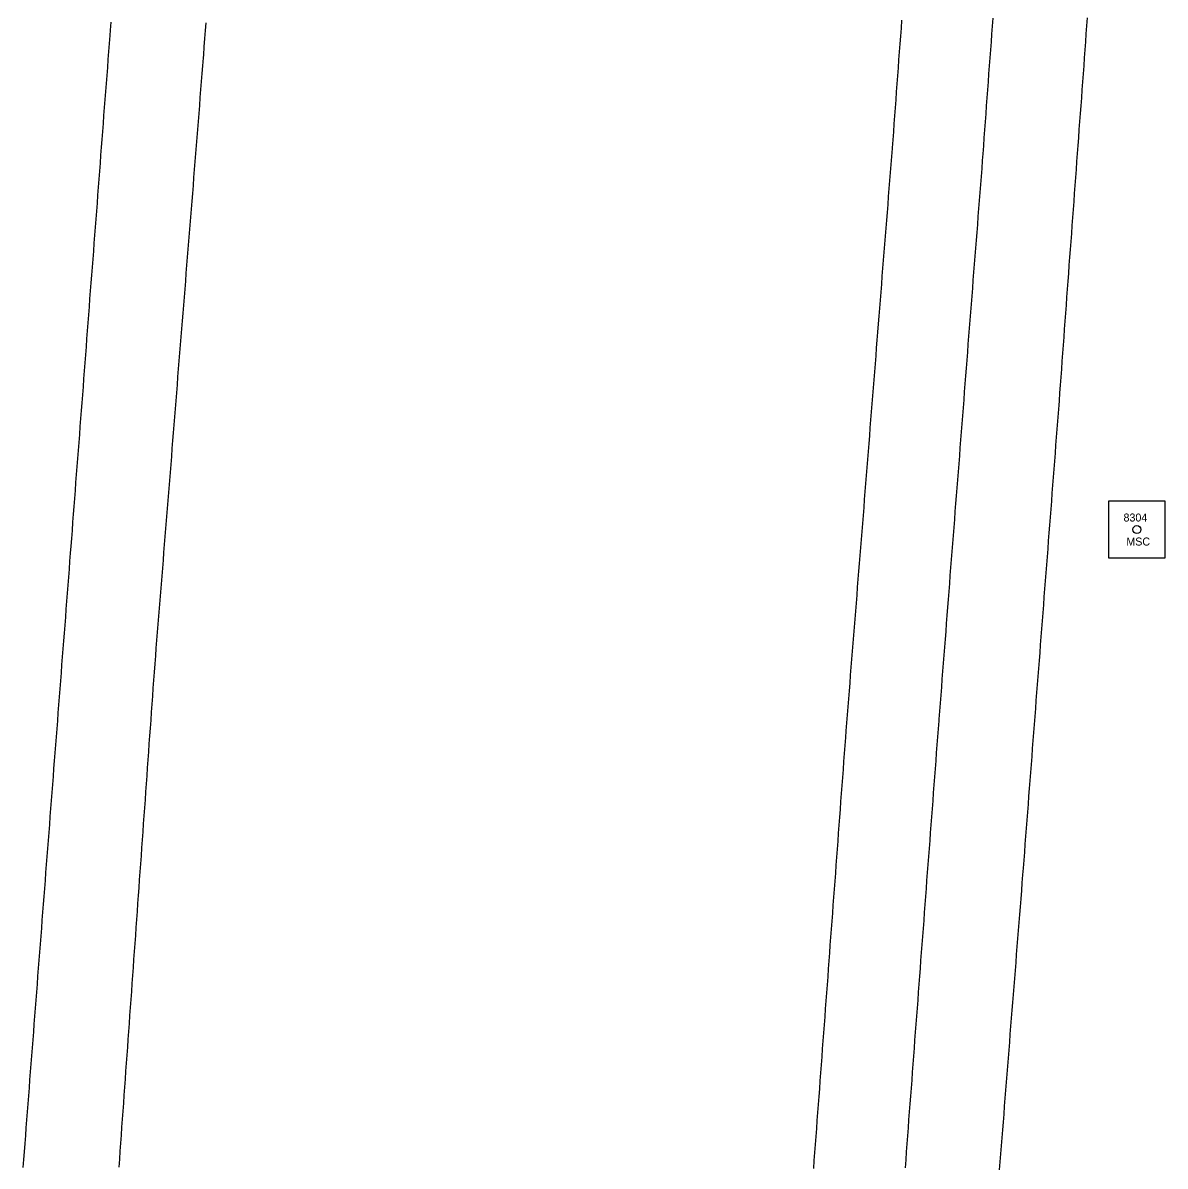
# Model space of a CAD drawing. Extents: x 205929 to 2357175, y -1785700 to 846739.
# Drawn here: x 2023419.5 to 2023562.3, y 809503.6 to 809646.4 of the extents above; entities that cross this region are included whole.
import ezdxf

# ---------------------------------------------------------------- set-up
doc = ezdxf.new("R2010")
doc.units = 0
for name, color, linetype in [('RD_HC_Survey', 7, 'Continuous'), ('RD_HC_txCode', 7, 'Continuous'), ('RD_Sketch1', 7, 'Continuous'), ('RD_SMD_Locator', 7, 'Continuous')]:
    doc.layers.add(name, color=color, linetype=linetype)

msp = doc.modelspace()

# ---------------------------------------------------------------- linework, layer by layer
at = {"layer": 'RD_HC_Survey'}
msp.add_lwpolyline([(2023562.28, 809586.65), (2023555.21, 809586.65), (2023555.21, 809579.58), (2023562.28, 809579.58)], close=True, dxfattribs=at)
msp.add_circle((2023558.75, 809583.11), 0.5, dxfattribs=at)
at = {"layer": 'RD_Sketch1'}
for points in [[(2023430.49, 809646.49), (2023430.41, 809645.49), (2023430.36, 809644.82), (2023430.29, 809643.83), (2023430.21, 809642.83), (2023430.13, 809641.83), (2023430.06, 809640.84), (2023429.98, 809639.84), (2023429.91, 809638.84), (2023429.83, 809637.85), (2023429.75, 809636.85), (2023429.68, 809635.85), (2023429.6, 809634.85), (2023429.53, 809633.86), (2023429.45, 809632.86), (2023429.37, 809631.86), (2023429.3, 809630.87), (2023429.22, 809629.87), (2023429.15, 809628.87), (2023429.07, 809627.88), (2023428.99, 809626.88), (2023428.92, 809625.88), (2023428.84, 809624.88), (2023428.77, 809623.89), (2023428.69, 809622.89), (2023428.61, 809621.89), (2023428.54, 809620.9), (2023428.46, 809619.9), (2023428.39, 809618.9), (2023428.31, 809617.91), (2023428.23, 809616.91), (2023428.16, 809615.91), (2023428.08, 809614.91), (2023428.01, 809613.92), (2023427.93, 809612.92), (2023427.85, 809611.92), (2023427.78, 809610.93), (2023427.7, 809609.93), (2023427.63, 809608.93), (2023427.55, 809607.94), (2023427.47, 809606.94), (2023427.4, 809605.94), (2023427.32, 809604.95), (2023427.25, 809603.95), (2023427.17, 809602.95), (2023427.09, 809601.95), (2023427.02, 809600.96), (2023426.94, 809599.96), (2023426.87, 809598.96), (2023426.79, 809597.97), (2023426.71, 809596.97), (2023426.64, 809595.97), (2023426.56, 809594.98), (2023426.48, 809593.98), (2023426.41, 809592.98), (2023426.33, 809591.98), (2023426.26, 809590.99), (2023426.18, 809589.99), (2023426.1, 809588.99), (2023426.03, 809588), (2023425.95, 809587), (2023425.88, 809586), (2023425.8, 809585.01), (2023425.72, 809584.01), (2023425.65, 809583.01), (2023425.57, 809582.01), (2023425.5, 809581.02), (2023425.5, 809581.02), (2023425.43, 809580.15), (2023425.35, 809579.16), (2023425.28, 809578.16), (2023425.2, 809577.16), (2023425.12, 809576.16), (2023425.05, 809575.17), (2023424.97, 809574.17), (2023424.89, 809573.17), (2023424.81, 809572.18), (2023424.74, 809571.18), (2023424.66, 809570.18), (2023424.58, 809569.19), (2023424.51, 809568.19), (2023424.43, 809567.19), (2023424.35, 809566.2), (2023424.27, 809565.2), (2023424.2, 809564.2), (2023424.12, 809563.2), (2023424.04, 809562.21), (2023423.97, 809561.21), (2023423.89, 809560.21), (2023423.81, 809559.22), (2023423.74, 809558.22), (2023423.66, 809557.22), (2023423.58, 809556.23), (2023423.5, 809555.23), (2023423.43, 809554.23), (2023423.35, 809553.24), (2023423.27, 809552.24), (2023423.2, 809551.24), (2023423.12, 809550.24), (2023423.04, 809549.25), (2023422.97, 809548.25), (2023422.89, 809547.25), (2023422.81, 809546.26), (2023422.73, 809545.26), (2023422.66, 809544.26), (2023422.58, 809543.27), (2023422.5, 809542.27), (2023422.43, 809541.27), (2023422.35, 809540.28), (2023422.27, 809539.28), (2023422.19, 809538.28), (2023422.12, 809537.28), (2023422.04, 809536.29), (2023421.96, 809535.29), (2023421.89, 809534.29), (2023421.81, 809533.3), (2023421.73, 809532.3), (2023421.66, 809531.3), (2023421.58, 809530.31), (2023421.5, 809529.31), (2023421.42, 809528.31), (2023421.35, 809527.32), (2023421.27, 809526.32), (2023421.19, 809525.32), (2023421.12, 809524.32), (2023421.04, 809523.33), (2023420.96, 809522.33), (2023420.89, 809521.33), (2023420.81, 809520.34), (2023420.73, 809519.34), (2023420.65, 809518.34), (2023420.58, 809517.35), (2023420.58, 809517.35), (2023420.5, 809516.35), (2023420.42, 809515.35), (2023420.35, 809514.36), (2023420.27, 809513.36), (2023420.19, 809512.36), (2023420.11, 809511.36), (2023420.04, 809510.37), (2023419.96, 809509.37), (2023419.88, 809508.37), (2023419.81, 809507.38), (2023419.73, 809506.38), (2023419.65, 809505.38), (2023419.58, 809504.39), (2023419.5, 809503.39)], [(2023442.36, 809646.43), (2023442.29, 809645.44), (2023442.21, 809644.44), (2023442.14, 809643.44), (2023442.07, 809642.44), (2023442.04, 809642.06), (2023441.96, 809641.06), (2023441.88, 809640.07), (2023441.8, 809639.07), (2023441.72, 809638.07), (2023441.64, 809637.08), (2023441.56, 809636.08), (2023441.48, 809635.08), (2023441.4, 809634.09), (2023441.32, 809633.09), (2023441.24, 809632.09), (2023441.17, 809631.1), (2023441.09, 809630.1), (2023441.01, 809629.1), (2023440.93, 809628.11), (2023440.85, 809627.11), (2023440.77, 809626.11), (2023440.69, 809625.11), (2023440.61, 809624.12), (2023440.53, 809623.12), (2023440.45, 809622.12), (2023440.37, 809621.13), (2023440.29, 809620.13), (2023440.21, 809619.13), (2023440.13, 809618.14), (2023440.05, 809617.14), (2023439.97, 809616.14), (2023439.89, 809615.15), (2023439.81, 809614.15), (2023439.73, 809613.15), (2023439.65, 809612.16), (2023439.57, 809611.16), (2023439.49, 809610.16), (2023439.41, 809609.17), (2023439.33, 809608.17), (2023439.25, 809607.17), (2023439.17, 809606.18), (2023439.09, 809605.18), (2023439.01, 809604.18), (2023438.93, 809603.19), (2023438.85, 809602.19), (2023438.77, 809601.19), (2023438.69, 809600.2), (2023438.61, 809599.2), (2023438.53, 809598.2), (2023438.46, 809597.21), (2023438.38, 809596.21), (2023438.3, 809595.21), (2023438.22, 809594.22), (2023438.14, 809593.22), (2023438.06, 809592.22), (2023437.98, 809591.23), (2023437.9, 809590.23), (2023437.82, 809589.23), (2023437.74, 809588.24), (2023437.66, 809587.24), (2023437.58, 809586.24), (2023437.5, 809585.25), (2023437.42, 809584.25), (2023437.34, 809583.25), (2023437.26, 809582.26), (2023437.18, 809581.26), (2023437.1, 809580.26), (2023437.02, 809579.27), (2023436.94, 809578.27), (2023436.94, 809578.27), (2023436.86, 809577.27), (2023436.78, 809576.28), (2023436.7, 809575.28), (2023436.62, 809574.28), (2023436.54, 809573.29), (2023436.46, 809572.29), (2023436.38, 809571.29), (2023436.3, 809570.3), (2023436.22, 809569.3), (2023436.14, 809568.3), (2023436.06, 809567.31), (2023435.98, 809566.31), (2023435.9, 809565.29), (2023435.83, 809564.3), (2023435.76, 809563.3), (2023435.69, 809562.3), (2023435.62, 809561.3), (2023435.55, 809560.31), (2023435.48, 809559.31), (2023435.41, 809558.31), (2023435.33, 809557.32), (2023435.26, 809556.32), (2023435.19, 809555.32), (2023435.12, 809554.32), (2023435.05, 809553.33), (2023434.98, 809552.33), (2023434.91, 809551.33), (2023434.84, 809550.33), (2023434.77, 809549.34), (2023434.69, 809548.34), (2023434.62, 809547.34), (2023434.55, 809546.34), (2023434.48, 809545.35), (2023434.41, 809544.35), (2023434.34, 809543.35), (2023434.27, 809542.35), (2023434.2, 809541.36), (2023434.13, 809540.36), (2023434.05, 809539.36), (2023433.98, 809538.36), (2023433.91, 809537.37), (2023433.84, 809536.37), (2023433.77, 809535.37), (2023433.7, 809534.37), (2023433.63, 809533.38), (2023433.56, 809532.38), (2023433.49, 809531.38), (2023433.41, 809530.38), (2023433.34, 809529.39), (2023433.27, 809528.39), (2023433.2, 809527.39), (2023433.13, 809526.4), (2023433.06, 809525.4), (2023432.99, 809524.4), (2023432.92, 809523.4), (2023432.85, 809522.41), (2023432.77, 809521.41), (2023432.7, 809520.41), (2023432.63, 809519.41), (2023432.56, 809518.42), (2023432.49, 809517.42), (2023432.42, 809516.42), (2023432.35, 809515.42), (2023432.28, 809514.43), (2023432.28, 809514.43), (2023432.21, 809513.43), (2023432.13, 809512.43), (2023432.06, 809511.43), (2023431.99, 809510.44), (2023431.92, 809509.44), (2023431.85, 809508.44), (2023431.78, 809507.44), (2023431.71, 809506.45), (2023431.64, 809505.45), (2023431.57, 809504.45), (2023431.5, 809503.45)], [(2023529.34, 809646.77), (2023529.27, 809645.77), (2023529.19, 809644.77), (2023529.12, 809643.78), (2023529.05, 809642.78), (2023528.97, 809641.78), (2023528.9, 809640.79), (2023528.82, 809639.79), (2023528.75, 809638.79), (2023528.68, 809637.8), (2023528.6, 809636.8), (2023528.53, 809635.8), (2023528.46, 809634.8), (2023528.38, 809633.81), (2023528.31, 809632.81), (2023528.23, 809631.81), (2023528.16, 809630.82), (2023528.15, 809630.72), (2023528.07, 809629.72), (2023527.99, 809628.72), (2023527.92, 809627.73), (2023527.84, 809626.73), (2023527.76, 809625.73), (2023527.68, 809624.74), (2023527.6, 809623.74), (2023527.52, 809622.74), (2023527.44, 809621.75), (2023527.36, 809620.75), (2023527.28, 809619.75), (2023527.2, 809618.76), (2023527.13, 809617.76), (2023527.05, 809616.76), (2023526.97, 809615.76), (2023526.89, 809614.77), (2023526.81, 809613.77), (2023526.73, 809612.77), (2023526.65, 809611.78), (2023526.57, 809610.78), (2023526.49, 809609.78), (2023526.41, 809608.79), (2023526.33, 809607.79), (2023526.26, 809606.79), (2023526.18, 809605.8), (2023526.1, 809604.8), (2023526.02, 809603.8), (2023525.94, 809602.81), (2023525.86, 809601.81), (2023525.78, 809600.81), (2023525.7, 809599.82), (2023525.62, 809598.82), (2023525.54, 809597.82), (2023525.46, 809596.83), (2023525.39, 809595.83), (2023525.31, 809594.83), (2023525.23, 809593.84), (2023525.15, 809592.84), (2023525.07, 809591.84), (2023524.99, 809590.85), (2023524.91, 809589.85), (2023524.83, 809588.85), (2023524.75, 809587.86), (2023524.67, 809586.86), (2023524.6, 809585.86), (2023524.52, 809584.87), (2023524.44, 809583.87), (2023524.36, 809582.87), (2023524.28, 809581.87), (2023524.2, 809580.88), (2023524.12, 809579.88), (2023524.04, 809578.88), (2023523.96, 809577.89), (2023523.88, 809576.89), (2023523.8, 809575.89), (2023523.73, 809574.9), (2023523.65, 809573.9), (2023523.57, 809572.9), (2023523.49, 809571.91), (2023523.41, 809570.91), (2023523.33, 809569.91), (2023523.25, 809568.92), (2023523.17, 809567.92), (2023523.09, 809566.92), (2023523.09, 809566.92), (2023523.01, 809565.93), (2023522.93, 809564.93), (2023522.86, 809563.93), (2023522.78, 809562.94), (2023522.7, 809561.94), (2023522.62, 809560.94), (2023522.54, 809559.95), (2023522.46, 809558.95), (2023522.38, 809557.95), (2023522.32, 809557.13), (2023522.24, 809556.13), (2023522.17, 809555.13), (2023522.09, 809554.14), (2023522.02, 809553.14), (2023521.95, 809552.14), (2023521.87, 809551.15), (2023521.8, 809550.15), (2023521.72, 809549.15), (2023521.65, 809548.15), (2023521.58, 809547.16), (2023521.5, 809546.16), (2023521.43, 809545.16), (2023521.35, 809544.17), (2023521.28, 809543.17), (2023521.21, 809542.17), (2023521.13, 809541.17), (2023521.06, 809540.18), (2023520.98, 809539.18), (2023520.91, 809538.18), (2023520.84, 809537.19), (2023520.76, 809536.19), (2023520.69, 809535.19), (2023520.61, 809534.19), (2023520.54, 809533.2), (2023520.47, 809532.2), (2023520.39, 809531.2), (2023520.32, 809530.21), (2023520.24, 809529.21), (2023520.17, 809528.21), (2023520.1, 809527.21), (2023520.02, 809526.22), (2023519.95, 809525.22), (2023519.87, 809524.22), (2023519.8, 809523.22), (2023519.73, 809522.23), (2023519.65, 809521.23), (2023519.58, 809520.23), (2023519.5, 809519.24), (2023519.43, 809518.24), (2023519.36, 809517.24), (2023519.28, 809516.24), (2023519.21, 809515.25), (2023519.13, 809514.25), (2023519.06, 809513.25), (2023518.99, 809512.26), (2023518.91, 809511.26), (2023518.84, 809510.26), (2023518.76, 809509.26), (2023518.69, 809508.27), (2023518.62, 809507.27), (2023518.54, 809506.27), (2023518.47, 809505.28), (2023518.39, 809504.28), (2023518.32, 809503.28)], [(2023540.73, 809647.02), (2023540.66, 809646.02), (2023540.59, 809645.02), (2023540.52, 809644.03), (2023540.44, 809643.03), (2023540.37, 809642.03), (2023540.3, 809641.04), (2023540.22, 809640.04), (2023540.15, 809639.04), (2023540.08, 809638.05), (2023540, 809637.05), (2023539.93, 809636.05), (2023539.86, 809635.05), (2023539.78, 809634.06), (2023539.71, 809633.06), (2023539.64, 809632.06), (2023539.56, 809631.07), (2023539.49, 809630.07), (2023539.43, 809629.22), (2023539.35, 809628.22), (2023539.27, 809627.22), (2023539.2, 809626.22), (2023539.12, 809625.23), (2023539.04, 809624.23), (2023538.96, 809623.23), (2023538.88, 809622.24), (2023538.81, 809621.24), (2023538.73, 809620.24), (2023538.65, 809619.25), (2023538.57, 809618.25), (2023538.5, 809617.25), (2023538.42, 809616.26), (2023538.34, 809615.26), (2023538.26, 809614.26), (2023538.19, 809613.26), (2023538.11, 809612.27), (2023538.03, 809611.27), (2023537.95, 809610.27), (2023537.88, 809609.28), (2023537.8, 809608.28), (2023537.72, 809607.28), (2023537.64, 809606.29), (2023537.57, 809605.29), (2023537.49, 809604.29), (2023537.41, 809603.29), (2023537.33, 809602.3), (2023537.25, 809601.3), (2023537.18, 809600.3), (2023537.1, 809599.31), (2023537.02, 809598.31), (2023536.94, 809597.31), (2023536.87, 809596.32), (2023536.79, 809595.32), (2023536.71, 809594.32), (2023536.63, 809593.33), (2023536.56, 809592.33), (2023536.48, 809591.33), (2023536.4, 809590.33), (2023536.32, 809589.34), (2023536.25, 809588.34), (2023536.17, 809587.34), (2023536.09, 809586.35), (2023536.01, 809585.35), (2023535.94, 809584.35), (2023535.86, 809583.36), (2023535.78, 809582.36), (2023535.7, 809581.36), (2023535.62, 809580.36), (2023535.55, 809579.37), (2023535.47, 809578.37), (2023535.39, 809577.37), (2023535.31, 809576.38), (2023535.24, 809575.38), (2023535.16, 809574.38), (2023535.08, 809573.39), (2023535, 809572.39), (2023534.93, 809571.39), (2023534.85, 809570.39), (2023534.77, 809569.4), (2023534.69, 809568.4), (2023534.62, 809567.4), (2023534.54, 809566.41), (2023534.46, 809565.41), (2023534.46, 809565.41), (2023534.38, 809564.41), (2023534.31, 809563.42), (2023534.23, 809562.42), (2023534.15, 809561.42), (2023534.07, 809560.43), (2023533.99, 809559.43), (2023533.98, 809559.19), (2023533.9, 809558.19), (2023533.83, 809557.2), (2023533.75, 809556.2), (2023533.68, 809555.2), (2023533.6, 809554.21), (2023533.53, 809553.21), (2023533.45, 809552.21), (2023533.38, 809551.22), (2023533.3, 809550.22), (2023533.23, 809549.22), (2023533.15, 809548.22), (2023533.08, 809547.23), (2023533, 809546.23), (2023532.93, 809545.23), (2023532.85, 809544.24), (2023532.77, 809543.24), (2023532.7, 809542.24), (2023532.62, 809541.25), (2023532.55, 809540.25), (2023532.47, 809539.25), (2023532.4, 809538.25), (2023532.32, 809537.26), (2023532.25, 809536.26), (2023532.17, 809535.26), (2023532.1, 809534.27), (2023532.02, 809533.27), (2023531.95, 809532.27), (2023531.87, 809531.28), (2023531.8, 809530.28), (2023531.72, 809529.28), (2023531.65, 809528.28), (2023531.57, 809527.29), (2023531.5, 809526.29), (2023531.42, 809525.29), (2023531.35, 809524.3), (2023531.27, 809523.3), (2023531.2, 809522.3), (2023531.12, 809521.31), (2023531.05, 809520.31), (2023530.97, 809519.31), (2023530.9, 809518.31), (2023530.82, 809517.32), (2023530.75, 809516.32), (2023530.67, 809515.32), (2023530.6, 809514.33), (2023530.52, 809513.33), (2023530.45, 809512.33), (2023530.37, 809511.34), (2023530.3, 809510.34), (2023530.22, 809509.34), (2023530.15, 809508.34), (2023530.07, 809507.35), (2023530, 809506.35), (2023529.92, 809505.35), (2023529.85, 809504.36), (2023529.77, 809503.36)], [(2023552.54, 809647.03), (2023552.47, 809646.04), (2023552.39, 809645.04), (2023552.32, 809644.04), (2023552.25, 809643.04), (2023552.17, 809642.05), (2023552.1, 809641.05), (2023552.03, 809640.05), (2023551.95, 809639.05), (2023551.88, 809638.06), (2023551.81, 809637.06), (2023551.73, 809636.06), (2023551.66, 809635.07), (2023551.59, 809634.07), (2023551.51, 809633.07), (2023551.44, 809632.07), (2023551.37, 809631.08), (2023551.29, 809630.08), (2023551.22, 809629.08), (2023551.15, 809628.09), (2023551.07, 809627.09), (2023551, 809626.09), (2023550.93, 809625.09), (2023550.85, 809624.1), (2023550.78, 809623.1), (2023550.71, 809622.1), (2023550.63, 809621.11), (2023550.56, 809620.11), (2023550.49, 809619.11), (2023550.41, 809618.11), (2023550.34, 809617.12), (2023550.26, 809616.12), (2023550.19, 809615.12), (2023550.12, 809614.13), (2023550.04, 809613.13), (2023549.97, 809612.13), (2023549.9, 809611.13), (2023549.82, 809610.14), (2023549.75, 809609.14), (2023549.68, 809608.14), (2023549.6, 809607.15), (2023549.53, 809606.15), (2023549.46, 809605.15), (2023549.38, 809604.15), (2023549.38, 809604.15), (2023549.31, 809603.16), (2023549.24, 809602.16), (2023549.16, 809601.16), (2023549.09, 809600.17), (2023549.02, 809599.17), (2023548.98, 809598.63), (2023548.9, 809597.63), (2023548.82, 809596.63), (2023548.75, 809595.64), (2023548.67, 809594.64), (2023548.59, 809593.64), (2023548.52, 809592.65), (2023548.44, 809591.65), (2023548.36, 809590.65), (2023548.29, 809589.66), (2023548.21, 809588.66), (2023548.13, 809587.66), (2023548.06, 809586.66), (2023547.98, 809585.67), (2023547.9, 809584.67), (2023547.83, 809583.67), (2023547.75, 809582.68), (2023547.68, 809581.68), (2023547.6, 809580.68), (2023547.52, 809579.69), (2023547.45, 809578.69), (2023547.37, 809577.69), (2023547.29, 809576.7), (2023547.22, 809575.7), (2023547.14, 809574.7), (2023547.06, 809573.7), (2023546.99, 809572.71), (2023546.91, 809571.71), (2023546.83, 809570.71), (2023546.76, 809569.72), (2023546.68, 809568.72), (2023546.6, 809567.72), (2023546.53, 809566.73), (2023546.45, 809565.73), (2023546.37, 809564.73), (2023546.3, 809563.73), (2023546.22, 809562.74), (2023546.14, 809561.74), (2023546.07, 809560.74), (2023545.99, 809559.75), (2023545.91, 809558.75), (2023545.84, 809557.75), (2023545.76, 809556.76), (2023545.68, 809555.76), (2023545.61, 809554.76), (2023545.53, 809553.76), (2023545.45, 809552.77), (2023545.38, 809551.77), (2023545.3, 809550.77), (2023545.22, 809549.78), (2023545.15, 809548.78), (2023545.07, 809547.78), (2023544.99, 809546.79), (2023544.92, 809545.79), (2023544.84, 809544.79), (2023544.76, 809543.79), (2023544.69, 809542.8), (2023544.61, 809541.8), (2023544.53, 809540.8), (2023544.53, 809540.8), (2023544.47, 809539.98), (2023544.39, 809538.98), (2023544.31, 809537.99), (2023544.23, 809536.99), (2023544.16, 809535.99), (2023544.08, 809535), (2023544, 809534), (2023543.92, 809533), (2023543.84, 809532.01), (2023543.76, 809531.01), (2023543.68, 809530.01), (2023543.6, 809529.02), (2023543.52, 809528.02), (2023543.44, 809527.02), (2023543.36, 809526.03), (2023543.29, 809525.03), (2023543.21, 809524.03), (2023543.13, 809523.04), (2023543.05, 809522.04), (2023542.97, 809521.04), (2023542.89, 809520.05), (2023542.81, 809519.05), (2023542.73, 809518.05), (2023542.65, 809517.06), (2023542.57, 809516.06), (2023542.5, 809515.06), (2023542.42, 809514.07), (2023542.34, 809513.07), (2023542.26, 809512.07), (2023542.18, 809511.08), (2023542.1, 809510.08), (2023542.02, 809509.08), (2023541.94, 809508.09), (2023541.86, 809507.09), (2023541.78, 809506.09), (2023541.7, 809505.1), (2023541.63, 809504.1), (2023541.55, 809503.1)]]:
    msp.add_lwpolyline(points, dxfattribs=at)
at = {"layer": 'RD_SMD_Locator'}
msp.add_circle((2023558.75, 809583.11), 0.001, dxfattribs=at)

# ---------------------------------------------------------------- texts
at = {"layer": 'RD_HC_txCode'}
for s, p in [('8304', (2023557.08, 809584.11)), ('MSC', (2023557.43, 809581.11))]:
    msp.add_text(s, height=1, dxfattribs=at).set_placement(p)

doc.saveas('drawing.dxf')
